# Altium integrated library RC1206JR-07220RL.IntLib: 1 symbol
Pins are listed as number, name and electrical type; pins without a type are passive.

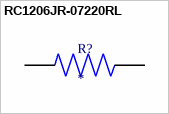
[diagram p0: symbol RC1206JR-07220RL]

## RC1206JR-07220RL
designator R?
220 Ohms Â±5% 0.25W, 1/4W Chip Resistor 1206 (3216 Metric) Thick Film; MF: Yageo; MP: RC1206JR-07220RL
footprint RESC3116X65N
pins: 1, 2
